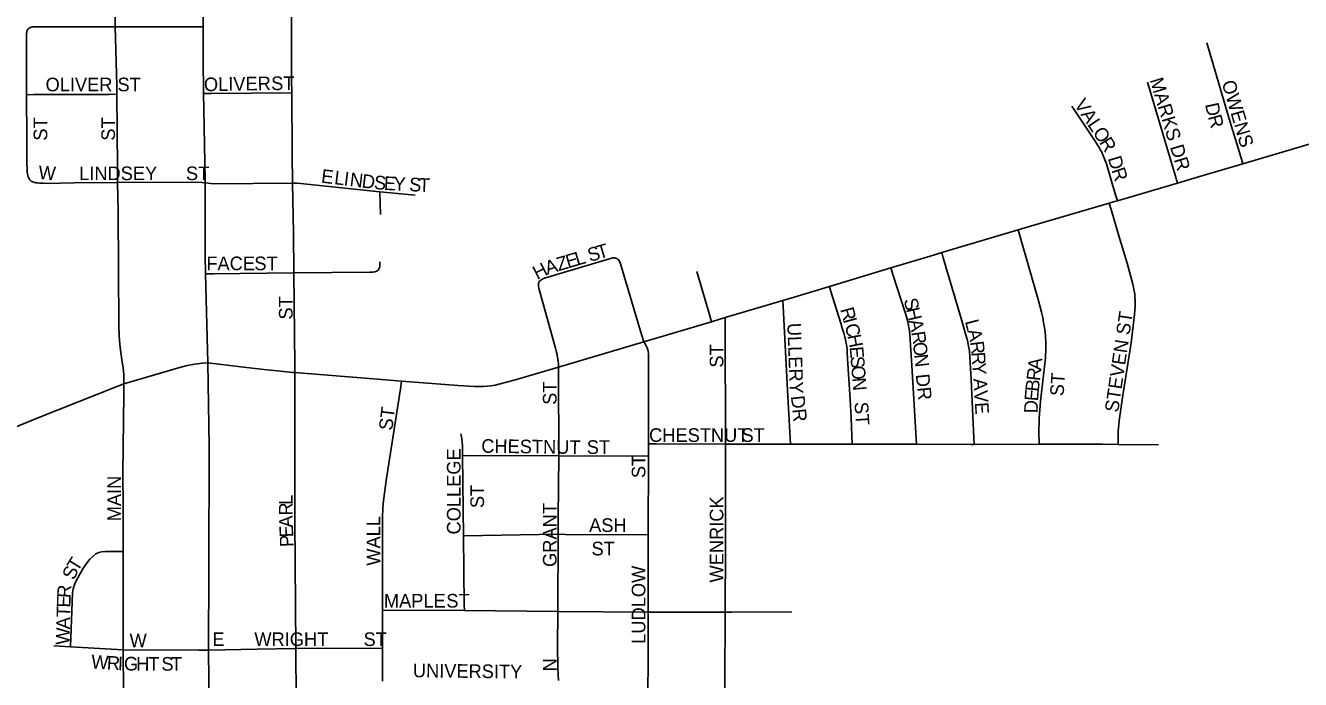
# Model space of a CAD drawing. Extents: x -87 to 2145, y -2128 to 440.
# Drawn here: x 137.52 to 160.89, y -597.78 to -585.79 of the extents above; entities that cross this region are included whole.
import ezdxf

# ---------------------------------------------------------------- set-up
doc = ezdxf.new("R2010")
doc.units = 0
for name, color, linetype in [('GM_X_City_Street', 7, 'Continuous'), ('GM_X_City_Street_Text', 7, 'Continuous'), ('GM_X_State_Route', 7, 'Continuous'), ('GM_X_US_Route', 7, 'Continuous')]:
    doc.layers.add(name, color=color, linetype=linetype)

msp = doc.modelspace()

# ---------------------------------------------------------------- linework, layer by layer
at = {"layer": 'GM_X_City_Street'}
for points in [[(139.163, -585.818), (139.159, -585.619), (139.15, -585.21), (139.148, -584.799), (139.156, -582.521)], [(142.399, -587.026), (142.397, -586.796), (142.395, -585.419)], [(137.538, -587.062), (137.535, -585.98), (137.538, -585.933), (137.539, -585.924), (137.541, -585.907), (137.544, -585.896), (137.548, -585.887), (137.555, -585.873), (137.559, -585.867), (137.569, -585.856), (137.582, -585.845)], [(137.582, -585.845), (137.603, -585.833), (137.613, -585.829), (137.623, -585.825), (137.633, -585.823), (137.652, -585.821), (137.67, -585.82), (137.777, -585.818), (139.163, -585.818)], [(139.163, -585.818), (140.659, -585.817), (140.772, -585.817)], [(139.191, -587.055), (139.189, -586.893), (139.163, -585.818)], [(159.836, -588.327), (159.798, -588.203), (159.603, -587.564), (159.178, -586.114)], [(158.638, -588.681), (158.595, -588.538), (158.089, -586.832)], [(137.538, -587.062), (137.673, -587.061), (139.054, -587.056), (139.191, -587.055)], [(137.599, -588.623), (137.577, -588.591), (137.565, -588.567), (137.557, -588.539), (137.549, -588.488), (137.546, -588.44), (137.545, -588.415), (137.543, -588.32), (137.54, -587.866), (137.538, -587.062)], [(139.206, -588.673), (139.202, -588.402), (139.191, -587.055)], [(140.783, -587.042), (140.924, -587.04), (142.399, -587.026)], [(142.414, -588.681), (142.406, -588.154), (142.399, -587.026)], [(157.536, -589.007), (157.497, -588.877), (157.334, -588.328), (157.296, -588.222), (157.269, -588.161), (157.249, -588.117), (157.221, -588.064), (157.2, -588.027), (157.179, -587.992), (157.128, -587.914), (156.702, -587.27)], [(137.599, -588.623), (137.624, -588.644), (137.647, -588.657), (137.672, -588.666), (137.706, -588.675), (137.736, -588.679), (137.772, -588.682), (137.839, -588.685), (137.938, -588.687), (138.15, -588.682), (138.412, -588.677), (139.206, -588.673)], [(139.206, -588.673), (140.687, -588.665), (140.748, -588.668), (140.813, -588.675)], [(139.323, -592.361), (139.318, -592.189), (139.307, -592.07), (139.281, -591.92), (139.253, -591.693), (139.24, -591.563), (139.234, -591.467), (139.227, -591.306), (139.215, -589.2), (139.206, -588.673)], [(140.813, -588.675), (140.914, -588.689), (140.968, -588.693), (142.414, -588.681)], [(142.414, -588.681), (142.454, -588.682), (142.486, -588.684), (142.501, -588.685), (142.557, -588.691), (144.014, -588.843)], [(142.435, -590.327), (142.428, -589.596), (142.414, -588.681)], [(144.014, -588.843), (144.66, -588.905)], [(144.024, -589.259), (144.014, -588.843)], [(157.548, -593.47), (157.548, -593.356), (157.548, -593.291), (157.55, -593.228), (157.555, -593.169), (157.56, -593.117), (157.571, -593.041), (157.633, -592.613), (157.787, -591.611), (157.853, -591.091), (157.863, -590.934), (157.864, -590.868), (157.862, -590.825), (157.858, -590.769), (157.854, -590.721), (157.849, -590.68), (157.845, -590.655), (157.833, -590.596), (157.817, -590.531), (157.714, -590.152), (157.564, -589.648), (157.422, -589.165), (157.388, -589.05)], [(156.101, -593.467), (156.1, -593.404), (156.097, -593.284), (156.103, -592.989), (156.127, -592.679), (156.203, -592.043), (156.218, -591.882), (156.227, -591.719), (156.224, -591.609), (156.216, -591.475), (156.204, -591.367), (156.184, -591.235), (156.167, -591.145), (156.144, -591.044), (156.084, -590.817), (155.755, -589.668), (155.718, -589.539)], [(154.911, -593.469), (154.906, -593.348), (154.857, -592.279), (154.833, -591.864), (154.822, -591.757), (154.814, -591.703), (154.801, -591.635), (154.786, -591.565), (154.766, -591.485), (154.671, -591.162), (154.345, -590.053), (154.316, -589.956)], [(143.981, -590.277), (143.996, -590.258), (144.003, -590.243), (144.009, -590.227), (144.011, -590.215), (144.014, -590.19), (144.015, -590.123)], [(146.933, -590.494), (146.95, -590.472), (146.966, -590.458), (146.982, -590.448), (147.002, -590.437), (147.031, -590.426), (148.245, -590.062), (148.266, -590.057), (148.283, -590.054), (148.303, -590.053), (148.319, -590.054), (148.333, -590.056), (148.357, -590.063)], [(148.854, -591.588), (148.814, -591.455), (148.424, -590.16), (148.413, -590.128), (148.406, -590.111), (148.396, -590.094), (148.391, -590.088), (148.374, -590.073), (148.357, -590.063)], [(153.853, -593.464), (153.769, -592.024), (153.731, -591.463), (153.722, -591.384), (153.714, -591.328), (153.707, -591.293), (153.686, -591.202), (153.667, -591.133), (153.644, -591.056), (153.426, -590.372), (153.383, -590.237)], [(140.818, -590.345), (140.966, -590.343), (142.435, -590.327)], [(142.435, -590.327), (143.83, -590.315), (143.857, -590.314), (143.891, -590.311), (143.919, -590.307), (143.942, -590.3), (143.962, -590.291), (143.981, -590.277)], [(142.455, -592.153), (142.453, -592.021), (142.435, -590.327)], [(150.094, -591.221), (150.038, -591.03), (149.824, -590.301)], [(147.29, -592.052), (147.288, -592.003), (147.282, -591.933), (147.279, -591.914), (147.273, -591.873), (147.267, -591.841), (147.262, -591.82), (147.254, -591.786), (147.246, -591.754), (147.232, -591.704), (146.945, -590.675), (146.934, -590.636), (146.926, -590.601), (146.922, -590.574), (146.92, -590.555), (146.92, -590.542), (146.921, -590.531), (146.924, -590.518), (146.933, -590.494)], [(152.674, -593.463), (152.654, -592.99), (152.648, -592.868), (152.637, -592.649), (152.589, -591.904), (152.581, -591.778), (152.579, -591.74), (152.574, -591.679), (152.569, -591.646), (152.565, -591.621), (152.559, -591.588), (152.55, -591.547), (152.538, -591.502), (152.519, -591.431), (152.492, -591.339), (152.465, -591.25), (152.285, -590.668), (152.256, -590.577)], [(151.543, -593.464), (151.486, -592.478), (151.407, -590.94), (151.401, -590.834)], [(150.35, -593.466), (150.346, -591.261), (150.346, -591.146)], [(148.939, -593.46), (148.938, -591.81), (148.933, -591.762), (148.928, -591.74), (148.913, -591.698), (148.898, -591.665), (148.885, -591.639), (148.854, -591.588)], [(147.294, -593.681), (147.292, -592.156), (147.29, -592.053), (147.29, -592.052)], [(142.473, -597.21), (142.456, -594.859), (142.458, -594.17), (142.455, -592.153)], [(144.064, -596.506), (144.063, -594.911), (144.061, -594.781), (144.067, -594.668), (144.069, -594.637), (144.073, -594.56), (144.078, -594.503), (144.127, -594.134), (144.39, -592.45), (144.411, -592.311)], [(139.31, -595.43), (139.305, -594.607), (139.302, -594.017), (139.321, -592.545), (139.323, -592.361)], [(145.531, -593.677), (145.531, -593.613), (145.529, -593.541), (145.528, -593.506), (145.527, -593.475), (145.525, -593.441), (145.522, -593.408), (145.519, -593.384), (145.516, -593.359), (145.511, -593.335), (145.503, -593.301), (145.496, -593.278)], [(148.938, -593.683), (148.939, -593.46)], [(148.939, -593.46), (149.081, -593.461), (150.35, -593.466)], [(150.343, -596.541), (150.349, -595.331), (150.352, -594.611), (150.35, -593.466)], [(150.35, -593.466), (150.838, -593.465), (151.543, -593.464)], [(151.543, -593.464), (152.674, -593.463)], [(152.674, -593.463), (152.723, -593.463), (153.674, -593.464), (153.853, -593.464)], [(153.853, -593.464), (154.856, -593.469), (154.911, -593.469)], [(154.911, -593.469), (156.101, -593.467)], [(156.101, -593.467), (156.283, -593.467), (157.267, -593.468), (157.548, -593.47)], [(157.548, -593.47), (158.291, -593.475)], [(145.531, -593.677), (145.644, -593.676), (147.294, -593.681)], [(145.546, -595.146), (145.531, -593.677)], [(147.284, -595.117), (147.286, -594.812), (147.294, -593.681)], [(147.294, -593.681), (148.938, -593.683)], [(148.936, -595.124), (148.938, -593.683)], [(145.546, -595.146), (147.284, -595.117)], [(145.563, -596.513), (145.559, -596.414), (145.546, -595.146)], [(147.275, -596.534), (147.284, -595.117)], [(147.284, -595.117), (147.417, -595.118), (148.936, -595.124)], [(148.931, -596.541), (148.936, -595.124)], [(138.344, -597.177), (138.377, -596.192), (138.39, -596.118), (138.412, -596.053), (138.436, -595.993), (138.511, -595.847), (138.571, -595.749), (138.638, -595.651), (138.699, -595.573), (138.751, -595.521), (138.807, -595.478), (138.861, -595.449), (138.913, -595.437), (138.978, -595.43), (139.172, -595.43), (139.31, -595.43)], [(139.31, -597.232), (139.31, -595.43)], [(144.063, -597.202), (144.064, -596.506)], [(144.064, -596.506), (145.563, -596.513)], [(145.563, -596.513), (147.275, -596.534)], [(147.29, -597.796), (147.282, -597.688), (147.275, -597.566), (147.271, -597.167), (147.275, -596.549), (147.275, -596.534)], [(147.275, -596.534), (148.931, -596.541)], [(148.85, -599.11), (148.886, -599.05), (148.913, -598.983), (148.921, -598.956), (148.927, -598.914), (148.931, -596.541)], [(148.931, -596.541), (150.343, -596.541)], [(150.335, -599.11), (150.343, -596.541)], [(150.343, -596.541), (150.465, -596.542), (151.565, -596.537)], [(138.037, -597.158), (138.344, -597.177)], [(138.344, -597.177), (139.31, -597.232)], [(139.321, -598.796), (139.31, -597.232)], [(139.31, -597.232), (140.694, -597.239), (140.875, -597.24)], [(140.875, -597.24), (141.763, -597.219), (142.473, -597.21)], [(142.473, -597.21), (144.063, -597.202)], [(142.487, -599.093), (142.473, -597.21)], [(144.065, -597.811), (144.063, -597.202)]]:
    msp.add_lwpolyline(points, dxfattribs=at)
at = {"layer": 'GM_X_State_Route'}
for points in [[(140.859, -591.978), (140.818, -590.345), (140.81, -590.017), (140.813, -588.675), (140.811, -588.628), (140.787, -587.333), (140.783, -587.042), (140.774, -586.399), (140.772, -585.817), (140.77, -585.417), (140.769, -585.156), (140.772, -584.348), (140.772, -584.124), (140.774, -583.879), (140.79, -581.654), (140.789, -581.158), (140.793, -579.234), (140.801, -579.139)], [(140.878, -595.759), (140.882, -593.498), (140.859, -591.978)], [(140.891, -598.796), (140.875, -597.263), (140.875, -597.24), (140.878, -595.759)]]:
    msp.add_lwpolyline(points, dxfattribs=at)
at = {"layer": 'GM_X_US_Route'}
for points in [[(154.441, -589.919), (155.718, -589.539), (155.941, -589.472), (157.388, -589.05), (157.484, -589.022), (157.536, -589.007), (158.638, -588.681), (159.025, -588.567), (159.836, -588.327), (161.218, -587.917), (163.042, -587.391)], [(142.193, -592.127), (142.412, -592.15), (142.455, -592.153), (143.215, -592.215), (144.047, -592.283), (144.411, -592.311), (145.452, -592.393), (145.746, -592.409), (145.908, -592.408), (145.984, -592.402), (146.052, -592.394), (146.127, -592.382), (146.194, -592.369), (146.479, -592.292), (147.29, -592.052), (148.854, -591.588), (150.094, -591.221), (150.346, -591.146), (151.401, -590.834), (151.611, -590.772), (152.256, -590.577), (153.383, -590.237), (154.102, -590.019), (154.316, -589.956), (154.441, -589.919)], [(140.008, -592.158), (140.32, -592.065), (140.48, -592.026), (140.619, -591.998), (140.76, -591.983), (140.859, -591.978)], [(140.859, -591.978), (141.468, -592.046), (141.886, -592.096), (142.193, -592.127)], [(132.681, -594.821), (133.078, -594.713), (133.336, -594.645), (133.532, -594.589), (133.707, -594.535), (134.033, -594.428), (134.315, -594.333), (134.528, -594.258), (134.878, -594.127), (135.35, -593.942), (135.718, -593.803), (136.129, -593.641), (137.763, -592.975), (139.18, -592.412), (139.323, -592.361), (140.008, -592.158)]]:
    msp.add_lwpolyline(points, dxfattribs=at)

# ---------------------------------------------------------------- texts
at = {"layer": 'GM_X_City_Street_Text'}
for s, rotation, p in [('OLIVER ST', 0, (137.885, -587)), ('OLIVER', 1.1035, (140.791, -587)), ('ST', 0, (142.021, -586.978)), ('MARKS DR', 286.9274, (158.126, -586.792)), ('OWENS', 286.2592, (159.447, -586.837)), ('V', 303.5627, (156.734, -587.241)), ('D', 282.7055, (159.142, -587.24)), ('A', 303.5507, (156.856, -587.424)), ('R', 285.3498, (159.193, -587.466)), ('ST', 90, (137.916, -587.905)), ('ST', 90, (139.158, -587.905)), ('L', 303.5605, (156.978, -587.608)), ('O', 303.5628, (157.075, -587.755)), ('R', 301.2074, (157.195, -587.936)), ('W', 356.1132, (137.749, -588.608)), ('LINDSEY', 0, (138.501, -588.628)), ('ST', 0, (140.459, -588.628)), ('D', 286.8416, (157.358, -588.227)), ('E', 353.1816, (142.929, -588.673)), ('L', 353.1816, (143.169, -588.701)), ('I', 353.2136, (143.344, -588.722)), ('N', 353.165, (143.453, -588.735)), ('D', 353.1918, (143.672, -588.762)), ('S', 354.5979, (143.897, -588.788)), ('E', 356.9242, (144.083, -588.806)), ('Y', 357.3525, (144.261, -588.815)), ('S', 357.3527, (144.547, -588.829)), ('T', 357.3218, (144.723, -588.837)), ('R', 288.3077, (157.424, -588.444)), ('T', 16.452, (148.033, -590.079)), ('Z', 16.452, (147.294, -590.297)), ('E', 16.4493, (147.463, -590.247)), ('L', 16.452, (147.631, -590.197)), ('S', 16.4493, (147.864, -590.129)), ('FACE', 0, (140.833, -590.278)), ('ST', 0, (141.713, -590.278)), ('H', 27.1173, (146.899, -590.458)), ('A', 17.3566, (147.085, -590.362)), ('ST', 90, (142.414, -591.183)), ('R', 285.5033, (152.451, -590.995)), ('S', 283.4995, (153.617, -590.82)), ('I', 285.5101, (152.503, -591.185)), ('H', 283.4902, (153.658, -590.991)), ('L', 284.5531, (154.739, -591.215)), ('STEVEN ST', 81.6556, (157.551, -592.892)), ('ULLERY', 272.0462, (151.484, -591.248)), ('C', 285.5033, (152.533, -591.291)), ('A', 283.0184, (153.709, -591.205)), ('R', 278.544, (153.758, -591.414)), ('A', 283.8613, (154.783, -591.385)), ('ST', 90, (150.312, -592.063)), ('H', 281.1085, (152.585, -591.477)), ('O', 276.2304, (153.787, -591.607)), ('R', 277.3539, (154.834, -591.591)), ('E', 275.1561, (152.626, -591.686)), ('S', 274.5821, (152.642, -591.861)), ('N', 276.1194, (153.811, -591.826)), ('R', 273.9853, (154.859, -591.784)), ('O', 274.5186, (152.656, -592.036)), ('Y', 273.8163, (154.873, -591.981)), ('R', 83.6611, (156.117, -592.315)), ('A', 83.6607, (156.138, -592.118)), ('ST', 90, (147.254, -592.745)), ('N', 274.5186, (152.673, -592.255)), ('DR', 276.0111, (153.838, -592.19)), ('A', 273.8163, (154.892, -592.266)), ('B', 83.7336, (156.095, -592.511)), ('ST', 86.4186, (156.55, -592.593)), ('DR', 276.0123, (151.55, -592.587)), ('V', 273.8163, (154.907, -592.486)), ('E', 85.0752, (156.08, -592.685)), ('ST', 82.88, (144.241, -593.224)), ('ST', 273.5806, (152.716, -592.698)), ('E', 273.8132, (154.921, -592.705)), ('D', 88.9836, (156.076, -592.901)), ('CHESTNUT', 0, (148.951, -593.424)), ('ST', 0, (150.645, -593.424)), ('CHESTNUT', 359.2148, (145.872, -593.622)), ('ST', 0, (147.807, -593.644)), ('COLLEGE', 90, (145.494, -595.121)), ('ST', 90, (148.882, -594.087)), ('MAIN', 90, (139.268, -594.879)), ('ST', 90, (145.924, -594.637)), ('L', 90, (142.414, -594.577)), ('WENRICK', 90, (150.312, -596.001)), ('R', 90.0972, (142.415, -594.775)), ('GRANT', 90, (147.254, -595.715)), ('A', 91.5742, (142.421, -594.993)), ('WALL', 90, (144.02, -595.693)), ('ASH', 0, (147.851, -595.074)), ('E', 92.5595, (142.429, -595.168)), ('P', 92.5554, (142.436, -595.344)), ('ST', 0, (147.895, -595.504)), ('T', 58.1133, (138.473, -595.816)), ('S', 67.5188, (138.411, -595.969)), ('LUDLOW', 90, (148.882, -597.123)), ('R', 86.6585, (138.345, -596.289)), ('E', 88.4805, (138.34, -596.463)), ('MAPLE', 0, (144.089, -596.46)), ('ST', 0, (145.233, -596.46)), ('T', 88.4805, (138.336, -596.639)), ('A', 88.4784, (138.33, -596.859)), ('W', 88.4868, (138.322, -597.145)), ('W', 0, (139.425, -597.186)), ('E', 0, (140.943, -597.164)), ('WRIGHT', 0, (141.713, -597.164)), ('ST', 0, (143.715, -597.164)), ('W', 355.7425, (138.714, -597.571)), ('R', 356.5881, (139.003, -597.593)), ('I', 357.7734, (139.207, -597.605)), ('G', 358.5122, (139.32, -597.609)), ('H', 359.6662, (139.546, -597.615)), ('T', 359.9639, (139.767, -597.616)), ('S', 359.9956, (140.009, -597.616)), ('T', 359.9956, (140.185, -597.616)), ('UNIVERSITY', 359.3101, (144.618, -597.736)), ('N', 90, (147.254, -597.629))]:
    msp.add_text(s, height=0.25, rotation=rotation, dxfattribs=at).set_placement(p)

doc.saveas('drawing.dxf')
